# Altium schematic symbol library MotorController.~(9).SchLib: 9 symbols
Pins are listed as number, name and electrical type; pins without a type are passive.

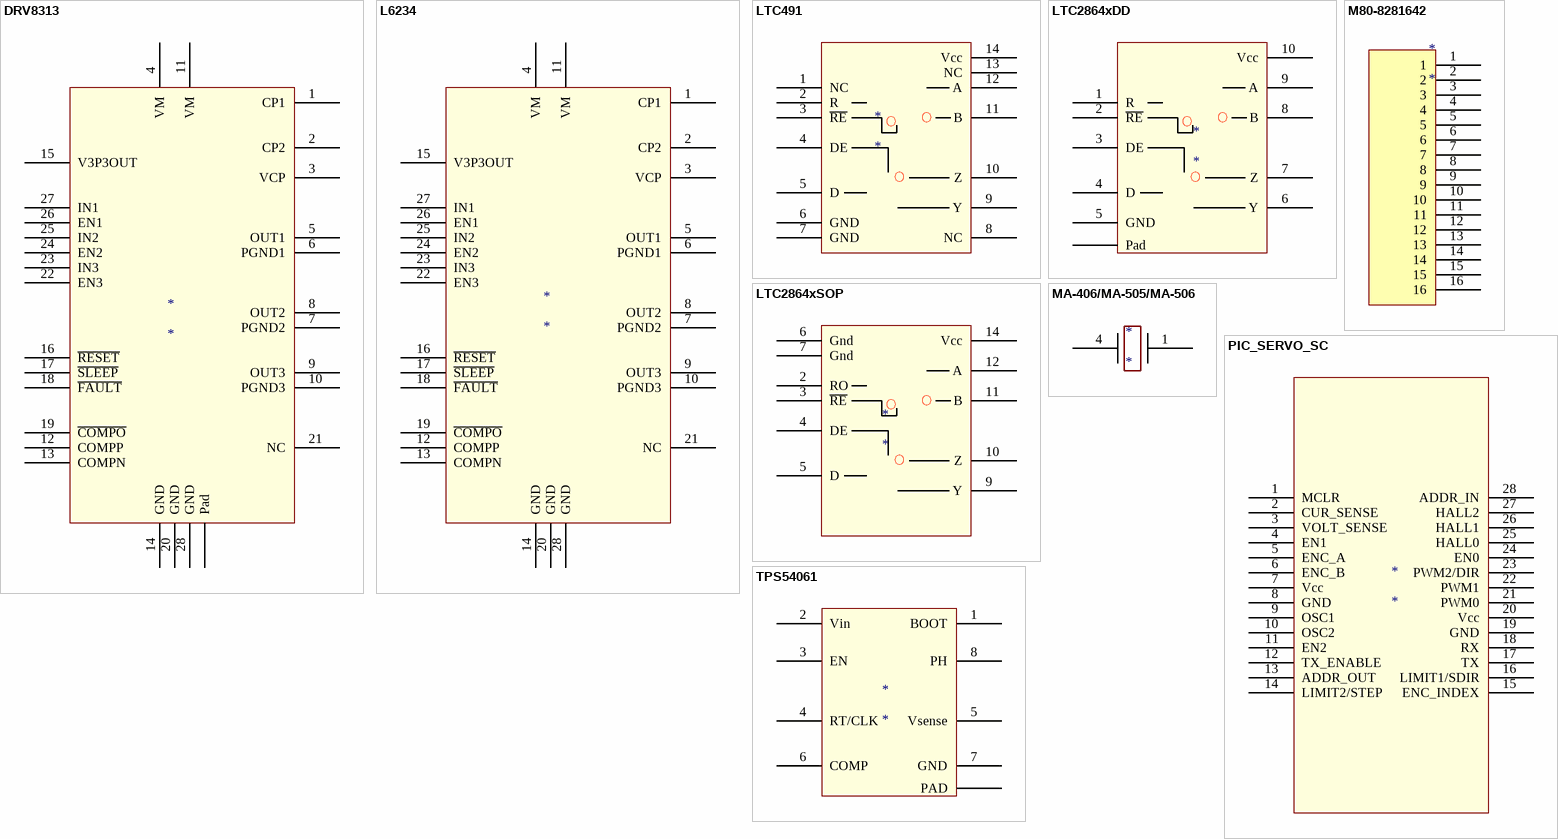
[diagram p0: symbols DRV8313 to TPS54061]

## DRV8313
designator *
footprint HTSSOP28 (HTTSSOP 28 Pin Package, TI)
pins: 1 CP1, 2 CP2, 3 VCP, 4 VM, 5 OUT1, 6 PGND1, 7 PGND2, 8 OUT2, 9 OUT3, 10 PGND3, 11 VM, 12 COMPP, 13 COMPN, 14 GND, 15 V3P3OUT, 16 ~{RESET}, 17 ~{SLEEP}, 18 ~{FAULT}, 19 ~{COMPO}, 20 GND, 21 NC, 22 EN3, 23 IN3, 24 EN2, 25 IN2, 26 EN1, 27 IN1, 28 GND, Pad

## L6234
designator *
pins: 1 CP1, 2 CP2, 3 VCP, 4 VM, 5 OUT1, 6 PGND1, 7 PGND2, 8 OUT2, 9 OUT3, 10 PGND3, 11 VM, 12 COMPP, 13 COMPN, 14 GND, 15 V3P3OUT, 16 ~{RESET}, 17 ~{SLEEP}, 18 ~{FAULT}, 19 ~{COMPO}, 20 GND, 21 NC, 22 EN3, 23 IN3, 24 EN2, 25 IN2, 26 EN1, 27 IN1, 28 GND

## LTC491
designator *
pins: 1 NC, 2 R, 3 ~{RE}, 4 DE, 5 D, 6 GND, 7 GND, 8 NC, 9 Y, 10 Z, 11 B, 12 A, 13 NC, 14 Vcc

## LTC2864xDD
designator *
footprint DD10
pins: 1 R, 2 ~{RE}, 3 DE, 4 D, 5 GND, 6 Y, 7 Z, 8 B, 9 A, 10 Vcc, Pad

## LTC2864xSOP
designator *
footprint SOP14
pins: 1 NC hidden, 2 RO, 3 ~{RE}, 4 DE, 5 D, 6 Gnd, 7 Gnd, 8 NC hidden, 9 Y, 10 Z, 11 B, 12 A, 13 NC hidden, 14 Vcc

## M80-8281642
designator *
pins: 1, 2, 3, 4, 5, 6, 7, 8, 9, 10, 11, 12, 13, 14, 15, 16

## MA-406/MA-505/MA-506
designator *
pins: 1, 4

## PIC_SERVO_SC
designator *
footprint SOP28
pins: 1 MCLR, 2 CUR_SENSE, 3 VOLT_SENSE, 4 EN1, 5 ENC_A, 6 ENC_B, 7 Vcc, 8 GND, 9 OSC1, 10 OSC2, 11 EN2, 12 TX_ENABLE, 13 ADDR_OUT, 14 LIMIT2/STEP, 15 ENC_INDEX, 16 LIMIT1/SDIR, 17 TX, 18 RX, 19 GND, 20 Vcc, 21 PWM0, 22 PWM1, 23 PWM2/DIR, 24 EN0, 25 HALL0, 26 HALL1, 27 HALL2, 28 ADDR_IN

## TPS54061
designator *
pins: 1 BOOT, 2 Vin, 3 EN, 4 RT/CLK, 5 Vsense, 6 COMP, 7 GND, 8 PH, PAD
